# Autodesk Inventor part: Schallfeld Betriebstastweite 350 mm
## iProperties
Shininess: 20.0
Length Units: 11269
Angle Units: 11279
Time Units: 11290
Mass Units: 11283
Length Display Precision: 2
Angle Display Precision: 2
Part Number: Schallfeld Betriebstastweite 350 mm
Material: Lexan (klar)
Document SubType Name: Modellieren
Description: Schallfeld 0,25 m
Checked By: Alves
Created: 2005-08
Designer: Klein
Manufacturer: Standard
Standards Organization: Custom
Density: 0.0
Volumn: 0.0
Area: 0.0
PropertySet Name: Model Information
Control State: 0
Master: False
Checked Out: False
Last Check In By: Kramp
Last Check In Date: 2005-08-11
ME: ST
Title: Schallfelder
Author: Klein
Comments: keine Bemerkung
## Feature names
1. Blindzone_Aussenglocke [Revolution]
